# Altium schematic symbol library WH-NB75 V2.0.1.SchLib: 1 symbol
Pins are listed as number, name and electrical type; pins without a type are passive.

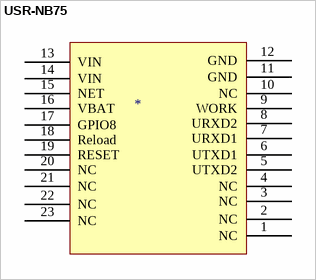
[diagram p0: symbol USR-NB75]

## USR-NB75
designator *
pins: 1 NC, 2 NC, 3 NC, 4 NC, 5 UTXD2, 6 UTXD1, 7 URXD1, 8 URXD2, 9 WORK, 10 NC, 11 GND, 12 GND, 13 VIN, 14 VIN, 15 NET, 16 VBAT, 17 GPIO8, 18 Reload, 19 RESET, 20 NC, 21 NC, 22 NC, 23 NC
